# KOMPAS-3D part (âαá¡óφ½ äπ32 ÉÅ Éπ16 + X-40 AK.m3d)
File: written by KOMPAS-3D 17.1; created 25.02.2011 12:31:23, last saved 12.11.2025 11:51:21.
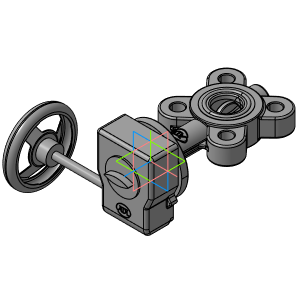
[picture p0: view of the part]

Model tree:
1. Плоскость XY
2. Плоскость ZX
3. Плоскость ZY
4. Ось X
5. Ось Y
6. Ось Z
7. Начало координат
8. Операция без истории:5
